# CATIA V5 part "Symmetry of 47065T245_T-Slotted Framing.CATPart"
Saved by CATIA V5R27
Part number: Symmetry of 47065T245_T-Slotted Framing
Bounding box of the stored display mesh (mm): x -3 to 38.1, y -38.1 to 3, z -3 to 38.1
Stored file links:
  \\triton.meca.polymtl.ca\usagers\zaoue\profiles\Desktop\varm_ass\structure prismatique\Symmetry of 47065T245_T-Slotted Framing.CATPart
  \\triton.meca.polymtl.ca\usagers\zaoue\profiles\Desktop\varm_ass\structure prismatique\3_cube.CATPart
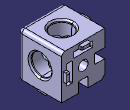
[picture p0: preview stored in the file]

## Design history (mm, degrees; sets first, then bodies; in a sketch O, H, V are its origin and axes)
Body1 (main body)
Body2 "Chamfer1"
  Solid1: linked copy from another document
